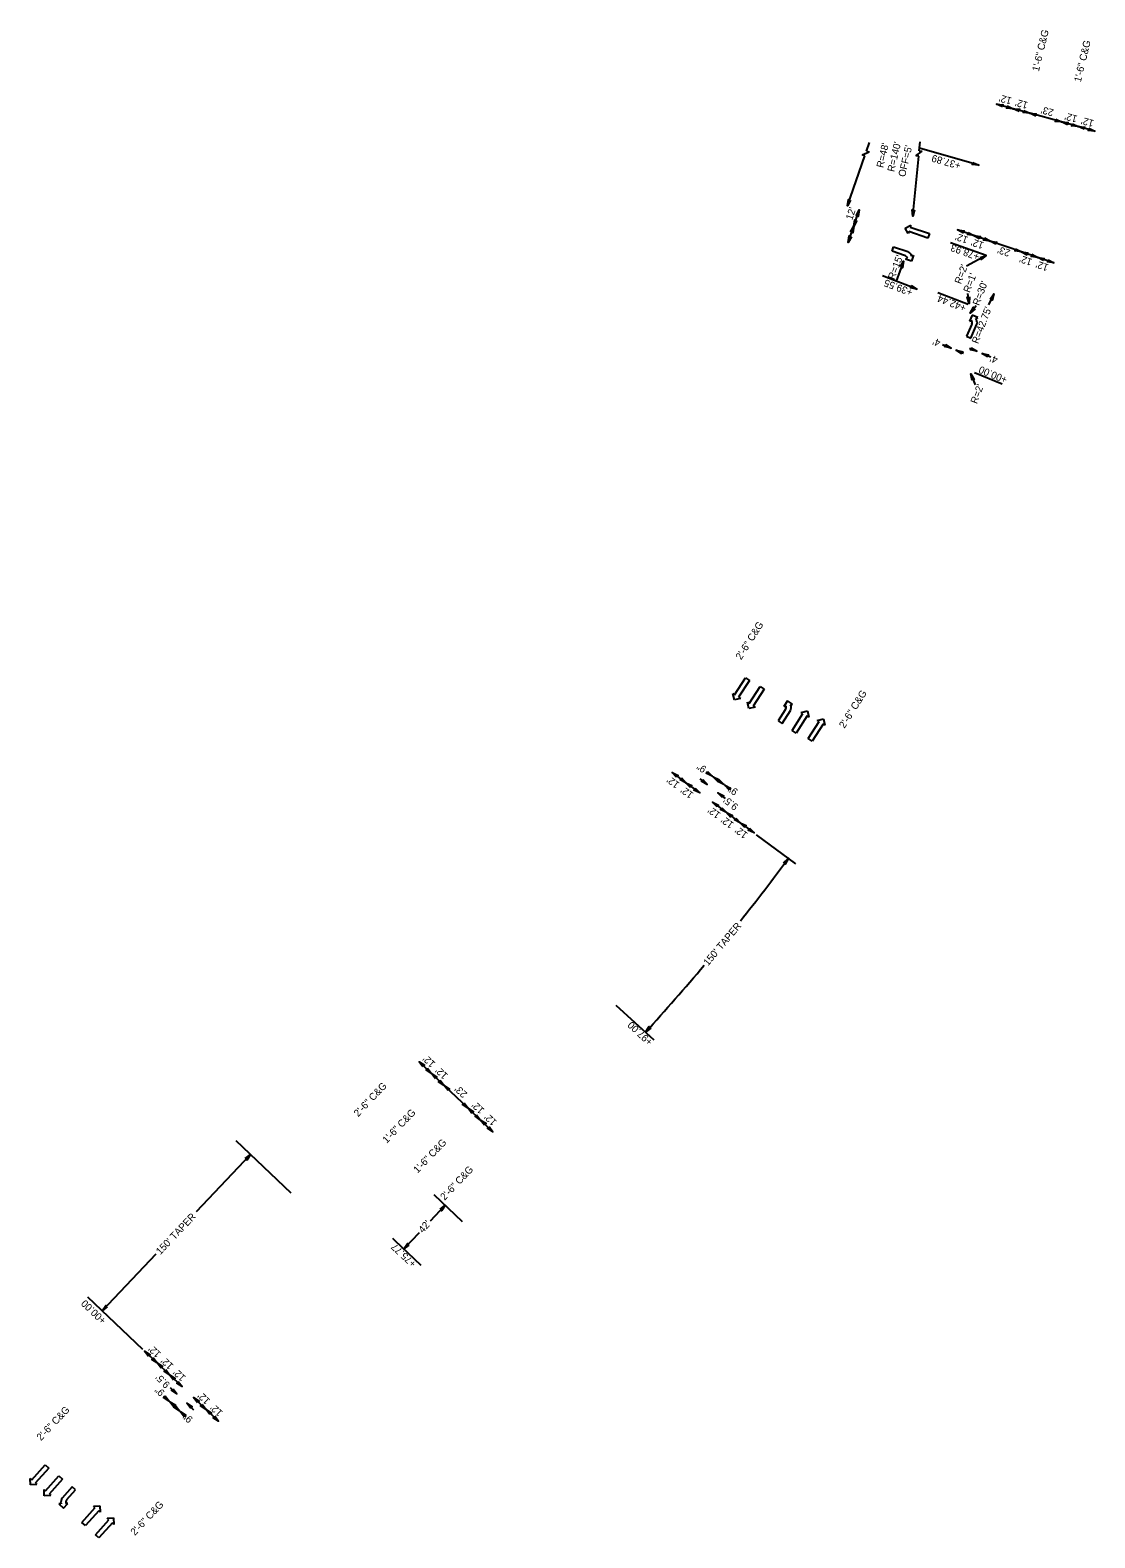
# Model space of a CAD drawing. Extents: x 2320991 to 2332664, y 598057 to 612602.
# Drawn here: x 2327678 to 2328419, y 603056 to 604106 of the extents above; entities that cross this region are included whole.
import ezdxf

# ---------------------------------------------------------------- set-up
doc = ezdxf.new("R2010")
doc.units = 0
for name, color, linetype in [('Prop Dimension', 7, 'Continuous'), ('Prop Dimension Text', 7, 'Continuous'), ('Prop Lane Arrow CELL', 7, 'Continuous'), ('Prop Terminator CELL', 7, 'Continuous')]:
    doc.layers.add(name, color=color, linetype=linetype)

msp = doc.modelspace()

# ---------------------------------------------------------------- linework, layer by layer
at = {"layer": 'Prop Dimension'}
for p, q in [((2328362.3, 604051.5), (2328350.7, 604054.7)), ((2328373.8, 604048.4), (2328362.3, 604051.5)), ((2328396, 604042.3), (2328373.8, 604048.4)), ((2328407.6, 604039.1), (2328396, 604042.3)), ((2328419.2, 604035.9), (2328407.6, 604039.1)), ((2328260.2, 604022), (2328262.3, 604027.9)), ((2328296.9, 604022.1), (2328297.5, 604028.4)), ((2328338.3, 604012.1), (2328297.1, 604024)), ((2328246.8, 603983.8), (2328259, 604018.6)), ((2328292.3, 603976.6), (2328296.5, 604018.5)), ((2328251.2, 603969.7), (2328255, 603981.1)), ((2328247.4, 603958.3), (2328251.2, 603969.7)), ((2328334.9, 603963.2), (2328323.6, 603967.1)), ((2328346.3, 603959.3), (2328334.9, 603963.2)), ((2328343.5, 603949.2), (2328318.7, 603958.1)), ((2328368, 603951.8), (2328346.3, 603959.3)), ((2328379.4, 603947.9), (2328368, 603951.8)), ((2328286, 603945.3), (2328280.7, 603931.5)), ((2328343.5, 603949.2), (2328329.7, 603941.9)), ((2328390.7, 603944.1), (2328379.4, 603947.9)), ((2328295.2, 603925.9), (2328271.3, 603935.1)), ((2328331, 603915.2), (2328309.8, 603923.4)), ((2328331.7, 603915.9), (2328330.6, 603922.8)), ((2328348.9, 603922.6), (2328345.2, 603915)), ((2328332.3, 603909.2), (2328336.6, 603914.4)), ((2328313, 603887.3), (2328319, 603884.8)), ((2328322.7, 603883.3), (2328327.8, 603881.2)), ((2328331.9, 603884.7), (2328337, 603882.6)), ((2328340.7, 603881.1), (2328346.8, 603878.6)), ((2328332.7, 603866.8), (2328335.8, 603859.1)), ((2328335.3, 603867.9), (2328354.6, 603859.9)), ((2328124.8, 603589.2), (2328134.4, 603582.1)), ((2328144.1, 603584.9), (2328149.2, 603580.9)), ((2328148.4, 603589.8), (2328152.7, 603586.7)), ((2328153.3, 603586.3), (2328157.5, 603583.2)), ((2328156.5, 603583.9), (2328160.8, 603580.9)), ((2328134.4, 603582.1), (2328144.1, 603575)), ((2328156.7, 603575.1), (2328161.8, 603571.1)), ((2328161.4, 603580.4), (2328165.6, 603577.4)), ((2328152.9, 603568.5), (2328162.6, 603561.3)), ((2328162.6, 603561.3), (2328172.2, 603554.2)), ((2328172.2, 603554.2), (2328181.9, 603547.1)), ((2328211, 603525.6), (2328183.5, 603545.9)), ((2328112.3, 603402.9), (2328085.9, 603427)), ((2327948.5, 603387.8), (2327957.2, 603379.6)), ((2327957.2, 603379.6), (2327965.9, 603371.3)), ((2327965.9, 603371.3), (2327982.6, 603355.5)), ((2327982.6, 603355.5), (2327991.3, 603347.2)), ((2327991.3, 603347.2), (2328000, 603339)), ((2327820.8, 603332.9), (2327859.1, 603296.5)), ((2327793.4, 603283.5), (2327831, 603323.1)), ((2327958.7, 603295.4), (2327978.6, 603276.6)), ((2327956.4, 603276.9), (2327966.8, 603287.8)), ((2327937.9, 603257.4), (2327948.9, 603268.9)), ((2327727.8, 603214.3), (2327765.5, 603254.1)), ((2327717.6, 603224), (2327755.9, 603187.6)), ((2327766.1, 603178), (2327757.4, 603186.2)), ((2327774.8, 603169.7), (2327766.1, 603178)), ((2327783.5, 603161.5), (2327774.8, 603169.7)), ((2327770.6, 603155.1), (2327774.4, 603151.5)), ((2327775.2, 603160.9), (2327779.9, 603156.4)), ((2327800.2, 603145.7), (2327791.5, 603153.9)), ((2327775, 603151), (2327778.8, 603147.4)), ((2327777.9, 603148.2), (2327781.7, 603144.6)), ((2327782.2, 603144.1), (2327786, 603140.5)), ((2327786.8, 603149.9), (2327791.5, 603145.4)), ((2327808.9, 603137.4), (2327800.2, 603145.7))]:
    msp.add_line(p, q, dxfattribs=at)
msp.add_lwpolyline([(2327929.9, 603265), (2327931.3, 603263.6), (2327949.7, 603246.1)], dxfattribs=at)
for start, end in [(321.4977, 323.5691), (317.6419, 319.9869)]:
    msp.add_arc((2326986.7, 604429.2), 1515.1, start, end, dxfattribs=at)
at = {"layer": 'Prop Dimension Text'}
for p, q in [((2328257.1, 604019.3), (2328262.1, 604021.4)), ((2328259, 604018.6), (2328257.1, 604019.3)), ((2328260.2, 604022), (2328262.1, 604021.4)), ((2328294.6, 604018.7), (2328298.9, 604021.9)), ((2328296.5, 604018.5), (2328294.6, 604018.7)), ((2328296.9, 604022.1), (2328298.9, 604021.9))]:
    msp.add_line(p, q, dxfattribs=at)
at = {"layer": 'Prop Lane Arrow CELL'}
for p, q in [((2328287.1, 603968.4), (2328291.1, 603970.5)), ((2328289.1, 603964.5), (2328287.1, 603968.4)), ((2328289.6, 603965.9), (2328289.1, 603964.5)), ((2328302.8, 603961.4), (2328289.6, 603965.9)), ((2328291.1, 603970.5), (2328290.6, 603969)), ((2328290.6, 603969), (2328303.9, 603964.6)), ((2328303.9, 603964.6), (2328302.8, 603961.4)), ((2328277.9, 603952.2), (2328278.9, 603955.3)), ((2328286.6, 603949.3), (2328277.9, 603952.2)), ((2328278.9, 603955.3), (2328288.9, 603952)), ((2328287.3, 603946.7), (2328288.6, 603947.4)), ((2328291.5, 603945.4), (2328287.3, 603946.7)), ((2328292.9, 603949.5), (2328291.5, 603945.4)), ((2328291.6, 603948.9), (2328292.9, 603949.5)), ((2328333.4, 603901.4), (2328329.8, 603893)), ((2328333.7, 603907.7), (2328331.9, 603903.6)), ((2328331.9, 603903.6), (2328333.3, 603904.2)), ((2328332.9, 603891.7), (2328337, 603901.4)), ((2328337.7, 603906), (2328333.7, 603907.7)), ((2328336.3, 603905.4), (2328337.7, 603906)), ((2328329.8, 603893), (2328332.9, 603891.7)), ((2328168.3, 603643.3), (2328175.9, 603655.2)), ((2328178.6, 603653.4), (2328171.1, 603641.6)), ((2328175.9, 603655.2), (2328178.6, 603653.4)), ((2328178.5, 603637.3), (2328186.1, 603649.1)), ((2328188.8, 603647.3), (2328181.3, 603635.5)), ((2328186.1, 603649.1), (2328188.8, 603647.3)), ((2328168.1, 603639.8), (2328167.1, 603644.2)), ((2328167.1, 603644.2), (2328168.3, 603643.3)), ((2328172.4, 603640.8), (2328168.1, 603639.8)), ((2328171.1, 603641.6), (2328172.4, 603640.8)), ((2328178.3, 603633.7), (2328177.3, 603638.1)), ((2328177.3, 603638.1), (2328178.5, 603637.3)), ((2328181.3, 603635.5), (2328182.6, 603634.7)), ((2328205, 603639.1), (2328202.5, 603635.3)), ((2328202.5, 603635.3), (2328204, 603635.6)), ((2328208.7, 603636.7), (2328205, 603639.1)), ((2328207.2, 603636.4), (2328208.7, 603636.7)), ((2328182.6, 603634.7), (2328178.3, 603633.7)), ((2328203.6, 603632.9), (2328198.7, 603625.2)), ((2328198.7, 603625.2), (2328201.5, 603623.4)), ((2328201.5, 603623.4), (2328207.2, 603632.3)), ((2328208.4, 603618.5), (2328215.9, 603630.3)), ((2328218.7, 603628.6), (2328211.2, 603616.7)), ((2328214.6, 603631.1), (2328219, 603632.1)), ((2328215.9, 603630.3), (2328214.6, 603631.1)), ((2328220, 603627.8), (2328218.7, 603628.6)), ((2328219, 603632.1), (2328220, 603627.8)), ((2328219.6, 603612.9), (2328227.1, 603624.7)), ((2328225.8, 603625.5), (2328230.1, 603626.5)), ((2328227.1, 603624.7), (2328225.8, 603625.5)), ((2328230.1, 603626.5), (2328231.1, 603622.1)), ((2328211.2, 603616.7), (2328208.4, 603618.5)), ((2328229.9, 603622.9), (2328222.4, 603611.1)), ((2328231.1, 603622.1), (2328229.9, 603622.9)), ((2328222.4, 603611.1), (2328219.6, 603612.9)), ((2327678.8, 603096.6), (2327688.1, 603107)), ((2327690.6, 603104.8), (2327681.2, 603094.4)), ((2327688.1, 603107), (2327690.6, 603104.8)), ((2327688.4, 603088.9), (2327697.7, 603099.3)), ((2327697.7, 603099.3), (2327700.2, 603097.1)), ((2327677.9, 603093.1), (2327677.6, 603097.6)), ((2327677.6, 603097.6), (2327678.8, 603096.6)), ((2327682.3, 603093.4), (2327677.9, 603093.1)), ((2327681.2, 603094.4), (2327682.3, 603093.4)), ((2327687.5, 603085.4), (2327687.3, 603089.9)), ((2327687.3, 603089.9), (2327688.4, 603088.9)), ((2327700.2, 603097.1), (2327690.8, 603086.7)), ((2327706.9, 603091.8), (2327699.9, 603083.9)), ((2327703.3, 603082.8), (2327709.3, 603089.6)), ((2327709.3, 603089.6), (2327706.9, 603091.8)), ((2327692, 603085.7), (2327687.5, 603085.4)), ((2327690.8, 603086.7), (2327692, 603085.7)), ((2327699.1, 603080), (2327697.7, 603079.9)), ((2327697.7, 603079.9), (2327700.9, 603076.9)), ((2327700.9, 603076.9), (2327703.9, 603080.2)), ((2327703.9, 603080.2), (2327702.5, 603080.2)), ((2327721.8, 603078.3), (2327726.2, 603078.6)), ((2327722.9, 603077.3), (2327721.8, 603078.3)), ((2327726.2, 603078.6), (2327726.5, 603074.1)), ((2327713.6, 603066.9), (2327722.9, 603077.3)), ((2327725.4, 603075.1), (2327716.1, 603064.7)), ((2327723.1, 603058.4), (2327732.4, 603068.8)), ((2327726.5, 603074.1), (2327725.4, 603075.1)), ((2327731.3, 603069.8), (2327735.7, 603070.1)), ((2327732.4, 603068.8), (2327731.3, 603069.8)), ((2327735.7, 603070.1), (2327736, 603065.6)), ((2327716.1, 603064.7), (2327713.6, 603066.9)), ((2327725.5, 603056.2), (2327723.1, 603058.4)), ((2327734.9, 603066.6), (2327725.5, 603056.2)), ((2327736, 603065.6), (2327734.9, 603066.6))]:
    msp.add_line(p, q, dxfattribs=at)
for centre, radius, start, end in [((2328286.6, 603947.3), 5.25, 17.5286, 62.8403), ((2328285.6, 603946.2), 3.27, 21.8582, 71.5164), ((2328330.4, 603902.7), 3.27, 337.3163, 26.9745), ((2328331.9, 603902.7), 5.25, 345.9924, 31.304), ((2328200.9, 603634.6), 3.27, 327.7255, 17.3837), ((2328202.4, 603634.4), 5.25, 336.4016, 21.7133), ((2327704.3, 603081.1), 5.25, 147.0628, 192.3745), ((2327705.7, 603080.6), 3.27, 138.3867, 188.0449)]:
    msp.add_arc(centre, radius, start, end, dxfattribs=at)
at = {"layer": 'Prop Terminator CELL'}
for points in [[(2328354.8, 604052.8), (2328350.7, 604054.7), (2328355.3, 604054.3), (2328354.5, 604053.7)], [(2328358.1, 604053.5), (2328362.3, 604051.5), (2328357.7, 604052), (2328358.5, 604052.6)], [(2328366.4, 604049.6), (2328362.3, 604051.5), (2328366.9, 604051.1), (2328366.1, 604050.5)], [(2328369.7, 604050.3), (2328373.8, 604048.4), (2328369.3, 604048.8), (2328370, 604049.4)], [(2328378, 604046.4), (2328373.8, 604048.4), (2328378.4, 604047.9), (2328377.7, 604047.3)], [(2328391.9, 604044.2), (2328396, 604042.3), (2328391.5, 604042.7), (2328392.2, 604043.3)], [(2328400.2, 604040.3), (2328396, 604042.3), (2328400.6, 604041.8), (2328399.8, 604041.2)], [(2328403.5, 604041), (2328407.6, 604039.1), (2328403, 604039.5), (2328403.8, 604040.1)], [(2328411.7, 604037.2), (2328407.6, 604039.1), (2328412.2, 604038.7), (2328411.4, 604038.1)], [(2328415, 604037.9), (2328419.2, 604035.9), (2328414.6, 604036.3), (2328415.4, 604037)], [(2328334.2, 604014.1), (2328338.3, 604012.1), (2328333.7, 604012.6), (2328334.5, 604013.2)], [(2328249, 603987.8), (2328246.8, 603983.8), (2328247.5, 603988.4), (2328248.1, 603987.6)], [(2328253.4, 603973.7), (2328251.2, 603969.7), (2328251.9, 603974.2), (2328252.5, 603973.4)], [(2328252.9, 603977), (2328255, 603981.1), (2328254.4, 603976.5), (2328253.8, 603977.3)], [(2328293.6, 603981), (2328292.3, 603976.6), (2328292, 603981.2), (2328292.7, 603980.5)], [(2328249.6, 603962.3), (2328247.4, 603958.3), (2328248.1, 603962.9), (2328248.7, 603962.1)], [(2328249.1, 603965.7), (2328251.2, 603969.7), (2328250.6, 603965.1), (2328250, 603965.9)], [(2328327.6, 603964.9), (2328323.6, 603967.1), (2328328.1, 603966.4), (2328327.3, 603965.8)], [(2328330.9, 603965.4), (2328334.9, 603963.2), (2328330.4, 603963.9), (2328331.2, 603964.5)], [(2328338.9, 603961), (2328334.9, 603963.2), (2328339.5, 603962.5), (2328338.7, 603961.9)], [(2328342.3, 603961.5), (2328346.3, 603959.3), (2328341.7, 603960), (2328342.5, 603960.6)], [(2328350.3, 603957.1), (2328346.3, 603959.3), (2328350.8, 603958.6), (2328350, 603958)], [(2328364, 603954), (2328368, 603951.8), (2328363.5, 603952.5), (2328364.3, 603953.1)], [(2328372, 603949.6), (2328368, 603951.8), (2328372.5, 603951.1), (2328371.7, 603950.5)], [(2328375.4, 603950.1), (2328379.4, 603947.9), (2328374.8, 603948.6), (2328375.6, 603949.2)], [(2328283.7, 603941.4), (2328286, 603945.3), (2328285.1, 603940.8), (2328284.6, 603941.6)], [(2328339.2, 603947.8), (2328343.5, 603949.2), (2328339.9, 603946.4), (2328340.1, 603947.4)], [(2328383.4, 603945.7), (2328379.4, 603947.9), (2328383.9, 603947.2), (2328383.1, 603946.7)], [(2328386.7, 603946.2), (2328390.7, 603944.1), (2328386.2, 603944.8), (2328387, 603945.3)], [(2328291.3, 603928.3), (2328295.2, 603925.9), (2328290.7, 603926.8), (2328291.5, 603927.4)], [(2328331.8, 603920.4), (2328331.7, 603915.9), (2328330.2, 603920.2), (2328331.1, 603919.8)], [(2328346.2, 603918.8), (2328348.9, 603922.6), (2328347.6, 603918.1), (2328347.2, 603919)], [(2328335.8, 603912.2), (2328332.3, 603909.2), (2328334.6, 603913.2), (2328334.8, 603912.2)], [(2328315.1, 603887.2), (2328319, 603884.8), (2328314.5, 603885.8), (2328315.3, 603886.3)], [(2328326.6, 603880.9), (2328322.7, 603883.3), (2328327.2, 603882.3), (2328326.4, 603881.8)], [(2328333.1, 603885), (2328337, 603882.6), (2328332.5, 603883.6), (2328333.3, 603884.1)], [(2328344.6, 603878.7), (2328340.7, 603881.1), (2328345.2, 603880.2), (2328344.4, 603879.6)], [(2328333.7, 603862.3), (2328332.7, 603866.8), (2328335.1, 603862.9), (2328334.2, 603863.1)], [(2328127.9, 603585.9), (2328124.8, 603589.2), (2328128.9, 603587.2), (2328127.9, 603586.9)], [(2328131.2, 603585.4), (2328134.4, 603582.1), (2328130.3, 603584.2), (2328131.2, 603584.5)], [(2328146.2, 603584.3), (2328149.2, 603580.9), (2328145.2, 603583.1), (2328146.1, 603583.4)], [(2328149.5, 603590), (2328152.7, 603586.7), (2328148.5, 603588.7), (2328149.5, 603589)], [(2328156.5, 603583), (2328153.3, 603586.3), (2328157.4, 603584.3), (2328156.5, 603584)], [(2328157.6, 603584.1), (2328160.8, 603580.9), (2328156.6, 603582.9), (2328157.6, 603583.2)], [(2328137.6, 603578.8), (2328134.4, 603582.1), (2328138.5, 603580.1), (2328137.6, 603579.8)], [(2328140.9, 603578.3), (2328144.1, 603575), (2328139.9, 603577), (2328140.9, 603577.3)], [(2328159.8, 603571.7), (2328156.7, 603575.1), (2328160.7, 603572.9), (2328159.8, 603572.6)], [(2328164.6, 603577.2), (2328161.4, 603580.4), (2328165.5, 603578.4), (2328164.6, 603578.1)], [(2328156.1, 603565.2), (2328152.9, 603568.5), (2328157, 603566.4), (2328156.1, 603566.1)], [(2328159.4, 603564.6), (2328162.6, 603561.3), (2328158.5, 603563.4), (2328159.4, 603563.7)], [(2328165.7, 603558), (2328162.6, 603561.3), (2328166.7, 603559.3), (2328165.8, 603559)], [(2328169.1, 603557.5), (2328172.2, 603554.2), (2328168.1, 603556.2), (2328169, 603556.5)], [(2328175.4, 603550.9), (2328172.2, 603554.2), (2328176.3, 603552.2), (2328175.4, 603551.9)], [(2328178.7, 603550.4), (2328181.9, 603547.1), (2328177.8, 603549.1), (2328178.7, 603549.4)], [(2328202.4, 603526.3), (2328205.7, 603529.5), (2328203.6, 603525.4), (2328203.3, 603526.3)], [(2328109.9, 603411.2), (2328106.3, 603408.4), (2328108.7, 603412.3), (2328108.9, 603411.4)], [(2327951.2, 603384.2), (2327948.5, 603387.8), (2327952.3, 603385.3), (2327951.4, 603385.1)], [(2327954.5, 603383.2), (2327957.2, 603379.6), (2327953.4, 603382.1), (2327954.3, 603382.3)], [(2327959.9, 603375.9), (2327957.2, 603379.6), (2327961, 603377), (2327960.1, 603376.9)], [(2327963.2, 603375), (2327965.9, 603371.3), (2327962.1, 603373.8), (2327963.1, 603374)], [(2327968.7, 603367.7), (2327965.9, 603371.3), (2327969.8, 603368.8), (2327968.8, 603368.6)], [(2327979.9, 603359.1), (2327982.6, 603355.5), (2327978.8, 603358), (2327979.7, 603358.2)], [(2327985.3, 603351.8), (2327982.6, 603355.5), (2327986.4, 603353), (2327985.5, 603352.8)], [(2327988.6, 603350.9), (2327991.3, 603347.2), (2327987.5, 603349.8), (2327988.5, 603349.9)], [(2327994.1, 603343.6), (2327991.3, 603347.2), (2327995.2, 603344.7), (2327994.2, 603344.5)], [(2327997.3, 603342.6), (2328000, 603339), (2327996.2, 603341.5), (2327997.2, 603341.7)], [(2327827.4, 603320.4), (2327831, 603323.1), (2327828.5, 603319.3), (2327828.3, 603320.3)], [(2327963.1, 603285.1), (2327966.8, 603287.8), (2327964.2, 603284), (2327964.1, 603285)], [(2327941.5, 603260.1), (2327937.9, 603257.4), (2327940.4, 603261.2), (2327940.6, 603260.2)], [(2327731.4, 603217), (2327727.8, 603214.3), (2327730.3, 603218.1), (2327730.5, 603217.1)], [(2327760.1, 603182.6), (2327757.4, 603186.2), (2327761.2, 603183.7), (2327760.3, 603183.5)], [(2327763.4, 603181.7), (2327766.1, 603178), (2327762.3, 603180.5), (2327763.2, 603180.7)], [(2327768.8, 603174.3), (2327766.1, 603178), (2327769.9, 603175.5), (2327769, 603175.3)], [(2327772.1, 603173.4), (2327774.8, 603169.7), (2327771, 603172.3), (2327771.9, 603172.5)], [(2327777.5, 603166.1), (2327774.8, 603169.7), (2327778.6, 603167.2), (2327777.7, 603167)], [(2327780.8, 603165.1), (2327783.5, 603161.5), (2327779.7, 603164), (2327780.7, 603164.2)], [(2327771.7, 603155.2), (2327774.4, 603151.5), (2327770.6, 603154), (2327771.6, 603154.2)], [(2327777.2, 603160.1), (2327779.9, 603156.4), (2327776.1, 603159), (2327777.1, 603159.1)], [(2327794.2, 603150.3), (2327791.5, 603153.9), (2327795.3, 603151.4), (2327794.4, 603151.2)], [(2327777.7, 603147.3), (2327775, 603151), (2327778.8, 603148.5), (2327777.8, 603148.3)], [(2327778.9, 603148.3), (2327781.7, 603144.6), (2327777.8, 603147.2), (2327778.8, 603147.4)], [(2327785, 603140.5), (2327782.2, 603144.1), (2327786.1, 603141.6), (2327785.1, 603141.4)], [(2327789.5, 603146.2), (2327786.8, 603149.9), (2327790.6, 603147.4), (2327789.7, 603147.2)], [(2327797.5, 603149.3), (2327800.2, 603145.7), (2327796.4, 603148.2), (2327797.3, 603148.4)], [(2327802.9, 603142), (2327800.2, 603145.7), (2327804, 603143.1), (2327803.1, 603142.9)], [(2327806.2, 603141.1), (2327808.9, 603137.4), (2327805.1, 603139.9), (2327806.1, 603140.1)]]:
    msp.add_lwpolyline(points, close=True, dxfattribs=at)

# ---------------------------------------------------------------- texts
at = {"layer": 'Prop Dimension'}
for s, rotation, p in [('+37.89', 163.8345, (2328326.2, 604013.9)), ('+78.93', 160.3282, (2328339.3, 603950.4)), ('+39.55', 159.0937, (2328292.8, 603925.5)), ('+42.44', 158.9914, (2328330, 603914.6)), ('+00.00', 157.5369, (2328358.7, 603864.6)), ('+97.00', 136.9918, (2328111.7, 603402.2)), ('+75.77', 136.9918, (2327947, 603247.7)), ('+00.00', 136.5265, (2327731, 603208.2))]:
    msp.add_text(s, height=5, rotation=rotation, dxfattribs=at).set_placement(p)
at = {"layer": 'Prop Dimension Text'}
for s, rotation, p in [('1\'-6" C&G', 76.4738, (2328380.2, 604077.1)), ('1\'-6" C&G', 76.4738, (2328409.4, 604069.7)), ("12'", 164.6449, (2328361.7, 604059.1)), ("12'", 164.6449, (2328373, 604056)), ("23'", 164.6449, (2328390.9, 604050.9)), ("12'", 164.6449, (2328407.4, 604046.5)), ("12'", 164.6449, (2328418.9, 604043.4)), ("R=48'", 76.7553, (2328271.8, 604010)), ("R=140'", 76.7553, (2328279.4, 604007.2)), ("OFF=5'", 76.7553, (2328287, 604003.7)), ("12'", 71.5098, (2328250.2, 603973.6)), ("12'", 161.1684, (2328331.3, 603962.1)), ("12'", 161.1684, (2328342.3, 603958.3)), ("R=15'", 69.0937, (2328279.5, 603932.1)), ("23'", 161.1684, (2328360.7, 603953)), ("R=2'", 69.0937, (2328325.9, 603929)), ("12'", 161.1684, (2328376, 603946.7)), ("12'", 161.1684, (2328387.4, 603942.9)), ("R=1'", 69.0937, (2328332, 603923)), ("R=30'", 69.0937, (2328338.5, 603914)), ("R=42.75'", 69.0937, (2328337.9, 603887.4)), ("4'", 157.7735, (2328312.2, 603890.2)), ("4'", 157.9606, (2328352.1, 603878.4)), ("R=2'", 69.0937, (2328337, 603845.6)), ('2\'-6" C&G', 57.6982, (2328172.8, 603667.3)), ('2\'-6" C&G', 57.6982, (2328244.8, 603619.6)), ('9"', 144.148, (2328149.2, 603592.6)), ("12'", 143.5744, (2328130.4, 603581.7)), ("12'", 143.5744, (2328140.1, 603574.6)), ('9"', 144.148, (2328171.1, 603576.9)), ("12'", 143.5744, (2328159, 603560.6)), ("9.5'", 141.9056, (2328171.3, 603566.3)), ("12'", 143.5744, (2328168.2, 603553.8)), ("12'", 143.5744, (2328177.9, 603546.7)), ("150' TAPER", 49.9059, (2328149.8, 603454.2)), ("12'", 136.5265, (2327960.3, 603386.8)), ("12'", 136.5265, (2327969, 603378.6)), ('2\'-6" C&G', 46.5265, (2327906.1, 603349.1)), ("23'", 136.5265, (2327982.5, 603365.7)), ('1\'-6" C&G', 46.1215, (2327926, 603330.6)), ("12'", 136.5265, (2327994.4, 603354.5)), ("12'", 136.5265, (2328003.1, 603346.2)), ('1\'-6" C&G', 46.1215, (2327947.5, 603309.8)), ('2\'-6" C&G', 46.5265, (2327966.3, 603290.9)), ("150' TAPER", 46.5265, (2327768.3, 603253)), ("42'", 48.2115, (2327951.2, 603268.1)), ("12'", 136.5265, (2327769.2, 603184.7)), ("12'", 136.5265, (2327777.9, 603176.4)), ("12'", 136.5265, (2327786.4, 603168.3)), ("9.5'", 134.7568, (2327775.4, 603163.3)), ('9"', 136.5265, (2327771.8, 603157.9)), ("12'", 136.5265, (2327803.5, 603152.1)), ('2\'-6" C&G', 46.5265, (2327685.2, 603123.5)), ("12'", 136.5265, (2327812.2, 603143.8)), ('9"', 136.5265, (2327791.4, 603139.3)), ('2\'-6" C&G', 46.5265, (2327750.6, 603057.5))]:
    msp.add_text(s, height=5, rotation=rotation, dxfattribs=at).set_placement(p)

doc.saveas('drawing.dxf')
